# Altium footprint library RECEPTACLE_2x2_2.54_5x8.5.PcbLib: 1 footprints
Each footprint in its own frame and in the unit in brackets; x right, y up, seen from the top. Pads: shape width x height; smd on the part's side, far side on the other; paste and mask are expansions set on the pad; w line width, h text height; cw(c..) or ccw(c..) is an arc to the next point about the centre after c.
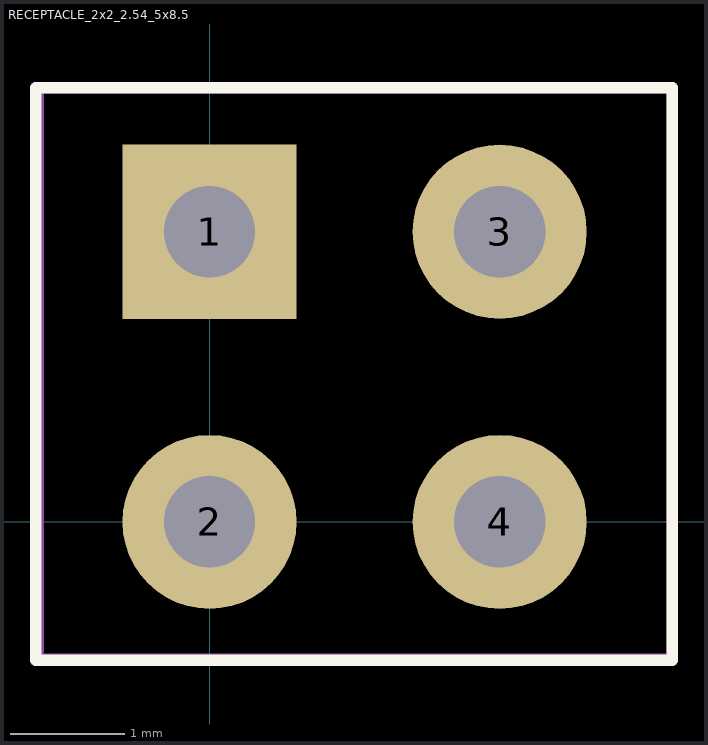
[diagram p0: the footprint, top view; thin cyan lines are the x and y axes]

## RECEPTACLE_2x2_2.54_5x8.5 [mil]
pads (4):
  rect 60x60 hole 31.5: 1(0,100)
  round 60 hole 31.5: 2(0,0) 3(100,100) 4(100,0)
Top Overlay:
  lines w3.94: -59.86,-47.64 159.45,-47.64 159.45,149.61 -59.86,149.61 -59.86,-47.64
Top Assembly:
  lines w3.94: -59.06,-47.24 -59.06,149.61 159.45,149.61 159.45,-47.24 -59.06,-47.24
  text "4" at 78.74,-23.62 h39.37
  text "3" at 80.71,76.77 h39.37
  text "2" at -19.68,-23.62 h39.37
  text "1" at -11.81,78.74 h39.37
  text ".Designator" at 25.59,31.5 h35.43
3D body "2x2_2.54mm_5x8.5.step": height 334.65, standoff -118.11, extent -59.84,-47.64 159.84,149.21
